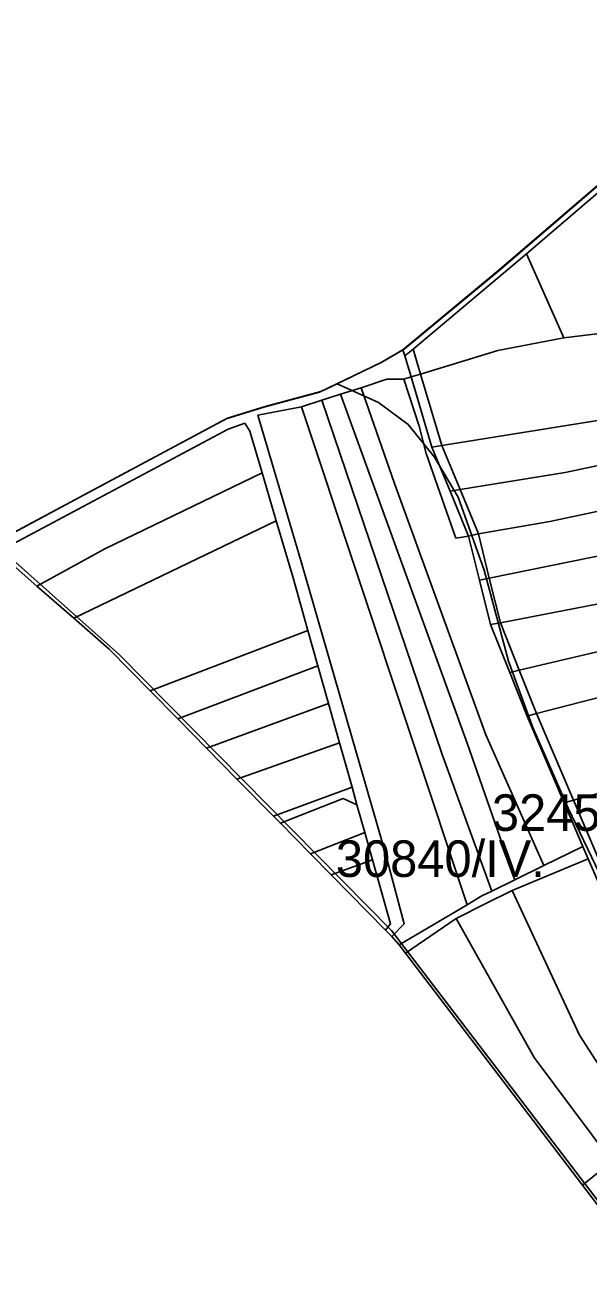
# Model space of a CAD drawing. Extents: x -535894 to -532827, y -1165802 to -1163635.
# Drawn here: x -535420 to -535189, y -1165071 to -1164561 of the extents above; entities that cross this region are included whole.
import ezdxf

# ---------------------------------------------------------------- set-up
doc = ezdxf.new("R2010")
doc.units = 0
for name, color, linetype in [('BPEJ_s', 7, 'Continuous'), ('orna_s', 7, 'Continuous'), ('ostatni_s', 7, 'Continuous'), ('PUPFL_s', 7, 'Continuous'), ('trav_porost_s', 7, 'Continuous')]:
    doc.layers.add(name, color=color, linetype=linetype)

msp = doc.modelspace()

# ---------------------------------------------------------------- linework, layer by layer
at = {"layer": 'BPEJ_s'}
for points in [[(-534930.369, -1164559.695), (-534935.616, -1164561.701), (-534945.728, -1164563.423), (-534957.21, -1164564.802), (-535000, -1164568.532), (-535001.057, -1164568.625), (-535054.023, -1164575.458), (-535100.616, -1164585.868), (-535112.034, -1164589.882), (-535117.371, -1164591.759), (-535121.179, -1164593.097), (-535123.817, -1164594.021), (-535156.991, -1164608.077), (-535174.047, -1164617.688), (-535225.782, -1164662.124), (-535264.558, -1164694.259), (-535273.775, -1164699.521), (-535285.222, -1164705.064), (-535292.152, -1164708.42), (-535298.828, -1164711.653), (-535321.651, -1164717.756), (-535337.207, -1164722.574), (-535394.549, -1164753.205), (-535432.662, -1164773.563)], [(-535176.39, -1164926.18), (-535197.26, -1164882.69), (-535211.75, -1164849.56), (-535221.79, -1164822.33), (-535231.819, -1164785.06), (-535242.49, -1164754.951), (-535252.21, -1164738.55), (-535263.04, -1164725.17), (-535275.15, -1164716.09), (-535292.152, -1164708.42), (-535285.222, -1164705.064), (-535273.775, -1164699.521), (-535264.558, -1164694.259), (-535225.782, -1164662.124), (-535174.047, -1164617.688)], [(-535432.662, -1164773.563), (-535394.549, -1164753.205), (-535337.207, -1164722.574), (-535321.651, -1164717.756), (-535298.828, -1164711.653), (-535292.152, -1164708.42), (-535275.15, -1164716.09), (-535263.04, -1164725.17), (-535252.21, -1164738.55), (-535242.49, -1164754.951), (-535231.819, -1164785.06), (-535221.79, -1164822.33), (-535211.75, -1164849.56), (-535197.26, -1164882.69), (-535176.39, -1164926.18), (-535174, -1164934.22)], [(-535433.191, -1164773.846), (-535381.625, -1164819.757), (-535269.853, -1164932.956), (-535148.539, -1165091.751)], [(-535148.539, -1165091.751), (-535269.853, -1164932.956), (-535381.625, -1164819.757), (-535433.191, -1164773.846)], [(-535149, -1165092.96), (-535191.37, -1165037.5), (-535264.1, -1164942.33), (-535266.73, -1164938.9), (-535269.72, -1164935.43), (-535272.25, -1164932.85), (-535294.62, -1164910.11), (-535303.11, -1164901.49), (-535315.47, -1164888.93), (-535318.27, -1164886.08), (-535333.29, -1164870.81), (-535345.77, -1164858.11), (-535357.66, -1164846.04), (-535369, -1164834.5), (-535385.74, -1164817.49), (-535400.34, -1164804.75), (-535415.52, -1164791.51), (-535431.57, -1164777.51)]]:
    msp.add_lwpolyline(points, dxfattribs=at)
at = {"layer": 'orna_s'}
for points in [[(-535171.93, -1164619.38), (-535148.68, -1164680.4), (-535165.07, -1164685.54), (-535198.96, -1164689.65), (-535214.35, -1164655.15), (-535175.47, -1164621.86)], [(-534690.65, -1164624.3), (-534680.75, -1164641.94), (-534685.32, -1164643.53), (-534716.28, -1164654.24), (-534820.53, -1164695.61), (-534882.6, -1164715.73), (-534930.6, -1164727.52), (-535229.64, -1164788.31), (-535234.09, -1164770.13), (-535204.83, -1164765.01), (-535150, -1164753.33), (-535058.34, -1164735.63), (-534985.67, -1164721.59), (-534954.93, -1164716.28), (-534891.05, -1164701.75), (-534872.36, -1164696.09), (-534859.96, -1164692.33), (-534823.37, -1164679.09), (-534731.01, -1164639.29), (-534694.91, -1164625.88)], [(-534685.32, -1164643.53), (-534680.75, -1164641.94), (-534669.21, -1164659.89), (-534675.43, -1164661.72), (-534705.37, -1164670.56), (-534787.37, -1164701.01), (-534856.21, -1164724.15), (-534931.28, -1164743.9), (-535012.13, -1164760.48), (-535158.6, -1164793.79), (-535225.1, -1164806.57), (-535229.64, -1164788.31), (-534930.6, -1164727.52), (-534882.6, -1164715.73), (-534820.53, -1164695.61), (-534716.28, -1164654.24)], [(-535198.96, -1164689.65), (-535226.15, -1164694.74), (-535257.9, -1164704.48), (-535260.94, -1164694.17), (-535214.35, -1164655.15)], [(-534669.21, -1164659.89), (-534657.84, -1164675.77), (-534662.44, -1164677.22), (-534691.34, -1164686.36), (-534795.22, -1164722.3), (-534932.16, -1164761.71), (-534978.25, -1164770.31), (-535087.47, -1164795.57), (-535217.32, -1164826.11), (-535225.1, -1164806.57), (-535158.6, -1164793.79), (-535012.13, -1164760.48), (-534931.28, -1164743.9), (-534856.21, -1164724.15), (-534787.37, -1164701.01), (-534705.37, -1164670.56), (-534675.43, -1164661.72)], [(-535109.38, -1164668.56), (-535103.22, -1164666.7), (-535094.01, -1164701.59), (-535093.03, -1164705.31), (-535183.44, -1164723.28), (-535249.16, -1164733.82), (-535257.9, -1164704.48), (-535226.15, -1164694.74), (-535198.96, -1164689.65), (-535165.07, -1164685.54), (-535148.68, -1164680.4), (-535148.51, -1164680.35), (-535137.84, -1164677.14), (-535128.9, -1164674.44), (-535118.94, -1164671.44)], [(-534662.44, -1164677.22), (-534657.84, -1164675.77), (-534648.21, -1164691.35), (-534794.04, -1164738.9), (-534925.58, -1164776.38), (-534981.55, -1164786.79), (-535087.94, -1164812.37), (-535210.21, -1164843.9), (-535217.32, -1164826.11), (-535087.47, -1164795.57), (-534978.25, -1164770.31), (-534932.16, -1164761.71), (-534795.22, -1164722.3), (-534691.34, -1164686.36)], [(-534644.26, -1164706.72), (-534642.29, -1164732.8), (-534729.01, -1164753.95), (-534823.37, -1164779.94), (-534931.7, -1164805.53), (-535046.65, -1164839.34), (-535194.99, -1164879.49), (-535210.21, -1164843.9), (-535087.94, -1164812.37), (-534981.55, -1164786.79), (-534925.58, -1164776.38), (-534794.04, -1164738.9), (-534648.21, -1164691.35)], [(-535065.86, -1164701.05), (-535062.16, -1164718.07), (-535156.56, -1164735.99), (-535198.52, -1164744.91), (-535241.65, -1164751.91), (-535249.16, -1164733.82), (-535183.44, -1164723.28), (-535093.03, -1164705.31)], [(-535062.16, -1164718.07), (-535058.34, -1164735.63), (-535150, -1164753.33), (-535204.83, -1164765.01), (-535234.09, -1164770.13), (-535241.65, -1164751.91), (-535198.52, -1164744.91), (-535156.56, -1164735.99)], [(-534729.01, -1164753.95), (-534642.29, -1164732.8), (-534639.25, -1164772.83), (-534705.71, -1164784.93), (-534805.56, -1164808.33), (-534871.85, -1164826.25), (-534989.4, -1164857.3), (-535007.79, -1164862.16), (-535095.84, -1164891.7), (-535170.48, -1164913.86), (-535177.9, -1164919.08), (-535185.4, -1164901.91), (-535194.99, -1164879.49), (-535046.65, -1164839.34), (-534931.7, -1164805.53), (-534823.37, -1164779.94)]]:
    msp.add_lwpolyline(points, close=True, dxfattribs=at)
at = {"layer": 'ostatni_s'}
msp.add_lwpolyline([(-535175.47, -1164621.86), (-535214.35, -1164655.15), (-535260.94, -1164694.17), (-535264.28, -1164696.97), (-535265.14, -1164694.54), (-535226.37, -1164662.4), (-535174.63, -1164617.97)], dxfattribs=at)
for points in [[(-535260.94, -1164694.17), (-535257.9, -1164704.48), (-535261.71, -1164705.66), (-535264.28, -1164696.97)], [(-535261.71, -1164705.66), (-535257.9, -1164704.48), (-535249.16, -1164733.82), (-535253.23, -1164734.48)], [(-535249.16, -1164733.82), (-535241.65, -1164751.91), (-535245.75, -1164752.59), (-535253.23, -1164734.48)], [(-535245.75, -1164752.59), (-535241.65, -1164751.91), (-535234.09, -1164770.13), (-535238.13, -1164771.01)], [(-535238.13, -1164771.01), (-535234.09, -1164770.13), (-535229.64, -1164788.31), (-535233.62, -1164789.13)], [(-535233.62, -1164789.13), (-535229.64, -1164788.31), (-535225.1, -1164806.57), (-535229.1, -1164807.35)], [(-535225.1, -1164806.57), (-535217.32, -1164826.11), (-535221.25, -1164827.04), (-535229.1, -1164807.35)], [(-535221.25, -1164827.04), (-535217.32, -1164826.11), (-535210.21, -1164843.9), (-535214.13, -1164844.92)], [(-535210.21, -1164843.9), (-535194.99, -1164879.49), (-535198.89, -1164880.55), (-535214.13, -1164844.92)], [(-535198.89, -1164880.55), (-535194.99, -1164879.49), (-535185.4, -1164901.91), (-535177.9, -1164919.08), (-535181.28, -1164921.44), (-535189.08, -1164903.47), (-535191.25, -1164898.41)]]:
    msp.add_lwpolyline(points, close=True, dxfattribs=at)
at = {"layer": 'PUPFL_s'}
msp.add_lwpolyline([(-535121.76, -1164593.37), (-535124.4, -1164594.3), (-535157.57, -1164608.35), (-535174.63, -1164617.97), (-535226.37, -1164662.4), (-535265.14, -1164694.54), (-535274.36, -1164699.8), (-535299.42, -1164711.94), (-535322.24, -1164718.04), (-535337.8, -1164722.86), (-535434.81, -1164774.69), (-535538.55, -1164687.07), (-535605.04, -1164629.61), (-535329.84, -1164374.82)], close=True, dxfattribs=at)
at = {"layer": 'trav_porost_s'}
for points in [[(-535434.81, -1164774.69), (-535337.8, -1164722.86), (-535322.24, -1164718.04), (-535299.42, -1164711.94), (-535274.36, -1164699.8), (-535265.14, -1164694.54), (-535264.28, -1164696.97), (-535261.71, -1164705.66), (-535264.79, -1164706.6), (-535271.8, -1164706.52), (-535282.32, -1164710.05), (-535290.79, -1164712.78), (-535298.39, -1164715.22), (-535306.74, -1164717.91), (-535324.72, -1164721.28), (-535306.74, -1164781.96), (-535272.55, -1164900.37), (-535264.58, -1164930.21), (-535269.72, -1164935.43), (-535272.25, -1164932.85), (-535270.21, -1164930.28), (-535277.63, -1164903.97), (-535280.81, -1164892.67), (-535284.01, -1164881.32), (-535286.04, -1164874.13), (-535291.17, -1164855.92), (-535295.73, -1164839.71), (-535300.1, -1164824.22), (-535304.15, -1164809.81), (-535310.26, -1164788.12), (-535317.16, -1164764.78), (-535322.98, -1164745.04), (-535328.05, -1164727.88), (-535330.07, -1164724.66), (-535336.95, -1164727.03), (-535431.57, -1164777.51)], [(-535102.38, -1165082.03), (-535129.39, -1165064.5), (-535141.65, -1165049.71), (-535153.27, -1165037.38), (-535167.09, -1165017.44), (-535168.5, -1165015.08), (-535181.9, -1164992.48), (-535192.57, -1164975.97), (-535220.19, -1164916.49), (-535189.08, -1164903.47), (-535181.28, -1164921.44), (-535141.82, -1165011.33), (-535136.18, -1165022.4), (-535127.67, -1165040.76), (-535119.93, -1165050.16), (-535111.17, -1165055.54), (-535091.48, -1165072.37)]]:
    msp.add_lwpolyline(points, dxfattribs=at)
for points in [[(-535271.8, -1164706.52), (-535264.79, -1164706.6), (-535258.52, -1164725.9), (-535255.52, -1164737.11), (-535243.38, -1164771.85), (-535238.13, -1164771.01), (-535233.62, -1164789.13), (-535229.1, -1164807.35), (-535221.25, -1164827.04), (-535214.13, -1164844.92), (-535198.89, -1164880.55), (-535191.25, -1164898.41), (-535207.22, -1164906.27), (-535231.08, -1164852.62), (-535268.57, -1164749.4), (-535282.32, -1164710.05)], [(-535264.79, -1164706.6), (-535261.71, -1164705.66), (-535253.23, -1164734.48), (-535245.75, -1164752.59), (-535238.13, -1164771.01), (-535243.38, -1164771.85), (-535255.52, -1164737.11), (-535258.52, -1164725.9)], [(-535298.39, -1164715.22), (-535290.79, -1164712.78), (-535238.67, -1164856.05), (-535219.2, -1164912.17), (-535228.61, -1164916.81), (-535249.1, -1164860.22)], [(-535290.79, -1164712.78), (-535282.32, -1164710.05), (-535268.57, -1164749.4), (-535231.08, -1164852.62), (-535207.22, -1164906.27), (-535219.2, -1164912.17), (-535238.67, -1164856.05)], [(-535324.72, -1164721.28), (-535306.74, -1164717.91), (-535238.77, -1164922.41), (-535266.73, -1164938.9), (-535269.72, -1164935.43), (-535264.58, -1164930.21), (-535272.55, -1164900.37), (-535306.74, -1164781.96)], [(-535306.74, -1164717.91), (-535298.39, -1164715.22), (-535249.1, -1164860.22), (-535228.61, -1164916.81), (-535232.65, -1164918.79), (-535238.77, -1164922.41)], [(-535336.95, -1164727.03), (-535330.07, -1164724.66), (-535328.05, -1164727.88), (-535322.98, -1164745.04), (-535387.55, -1164776.28), (-535415.52, -1164791.51), (-535431.57, -1164777.51)], [(-535322.98, -1164745.04), (-535317.16, -1164764.78), (-535400.34, -1164804.75), (-535415.52, -1164791.51), (-535387.55, -1164776.28)], [(-535317.16, -1164764.78), (-535310.26, -1164788.12), (-535304.15, -1164809.81), (-535369, -1164834.5), (-535385.74, -1164817.49), (-535400.34, -1164804.75)], [(-535304.15, -1164809.81), (-535300.1, -1164824.22), (-535357.66, -1164846.04), (-535369, -1164834.5)], [(-535300.1, -1164824.22), (-535295.73, -1164839.71), (-535345.77, -1164858.11), (-535357.66, -1164846.04)], [(-535295.73, -1164839.71), (-535291.17, -1164855.92), (-535333.29, -1164870.81), (-535345.77, -1164858.11)], [(-535333.29, -1164870.81), (-535291.17, -1164855.92), (-535286.04, -1164874.13), (-535318.27, -1164886.08)], [(-535286.04, -1164874.13), (-535284.01, -1164881.32), (-535289.62, -1164878.78), (-535315.47, -1164888.93), (-535318.27, -1164886.08)], [(-535289.62, -1164878.78), (-535284.01, -1164881.32), (-535280.81, -1164892.67), (-535303.11, -1164901.49), (-535315.47, -1164888.93)], [(-535303.11, -1164901.49), (-535280.81, -1164892.67), (-535277.63, -1164903.97), (-535294.62, -1164910.11)], [(-535191.25, -1164898.41), (-535189.08, -1164903.47), (-535220.19, -1164916.49), (-535231.36, -1164922.07), (-535243.3, -1164928.03), (-535264.1, -1164942.33), (-535266.73, -1164938.9), (-535238.77, -1164922.41), (-535232.65, -1164918.79), (-535228.61, -1164916.81), (-535219.2, -1164912.17), (-535207.22, -1164906.27)], [(-535294.62, -1164910.11), (-535277.63, -1164903.97), (-535270.21, -1164930.28), (-535272.25, -1164932.85)], [(-535220.19, -1164916.49), (-535192.57, -1164975.97), (-535181.9, -1164992.48), (-535168.5, -1165015.08), (-535167.09, -1165017.44), (-535153.27, -1165037.38), (-535141.65, -1165049.71), (-535129.39, -1165064.5), (-535138.85, -1165078.22), (-535172.47, -1165036.89), (-535179.28, -1165027.8), (-535211.27, -1164985.05), (-535243.3, -1164928.03), (-535231.36, -1164922.07)], [(-535243.3, -1164928.03), (-535211.27, -1164985.05), (-535179.28, -1165027.8), (-535191.37, -1165037.5), (-535264.1, -1164942.33)], [(-535179.28, -1165027.8), (-535172.47, -1165036.89), (-535138.85, -1165078.22), (-535141.75, -1165082.45), (-535149, -1165092.96), (-535191.37, -1165037.5)]]:
    msp.add_lwpolyline(points, close=True, dxfattribs=at)

# ---------------------------------------------------------------- texts
at = {"layer": 'BPEJ_s'}
for s, p in [('32451/IV.', (-535228.576, -1164892.05)), ('30840/IV.', (-535292.681, -1164910.959))]:
    msp.add_text(s, height=15, dxfattribs=at).set_placement(p)

doc.saveas('drawing.dxf')
